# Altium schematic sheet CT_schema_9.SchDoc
size 382 x 278 mm
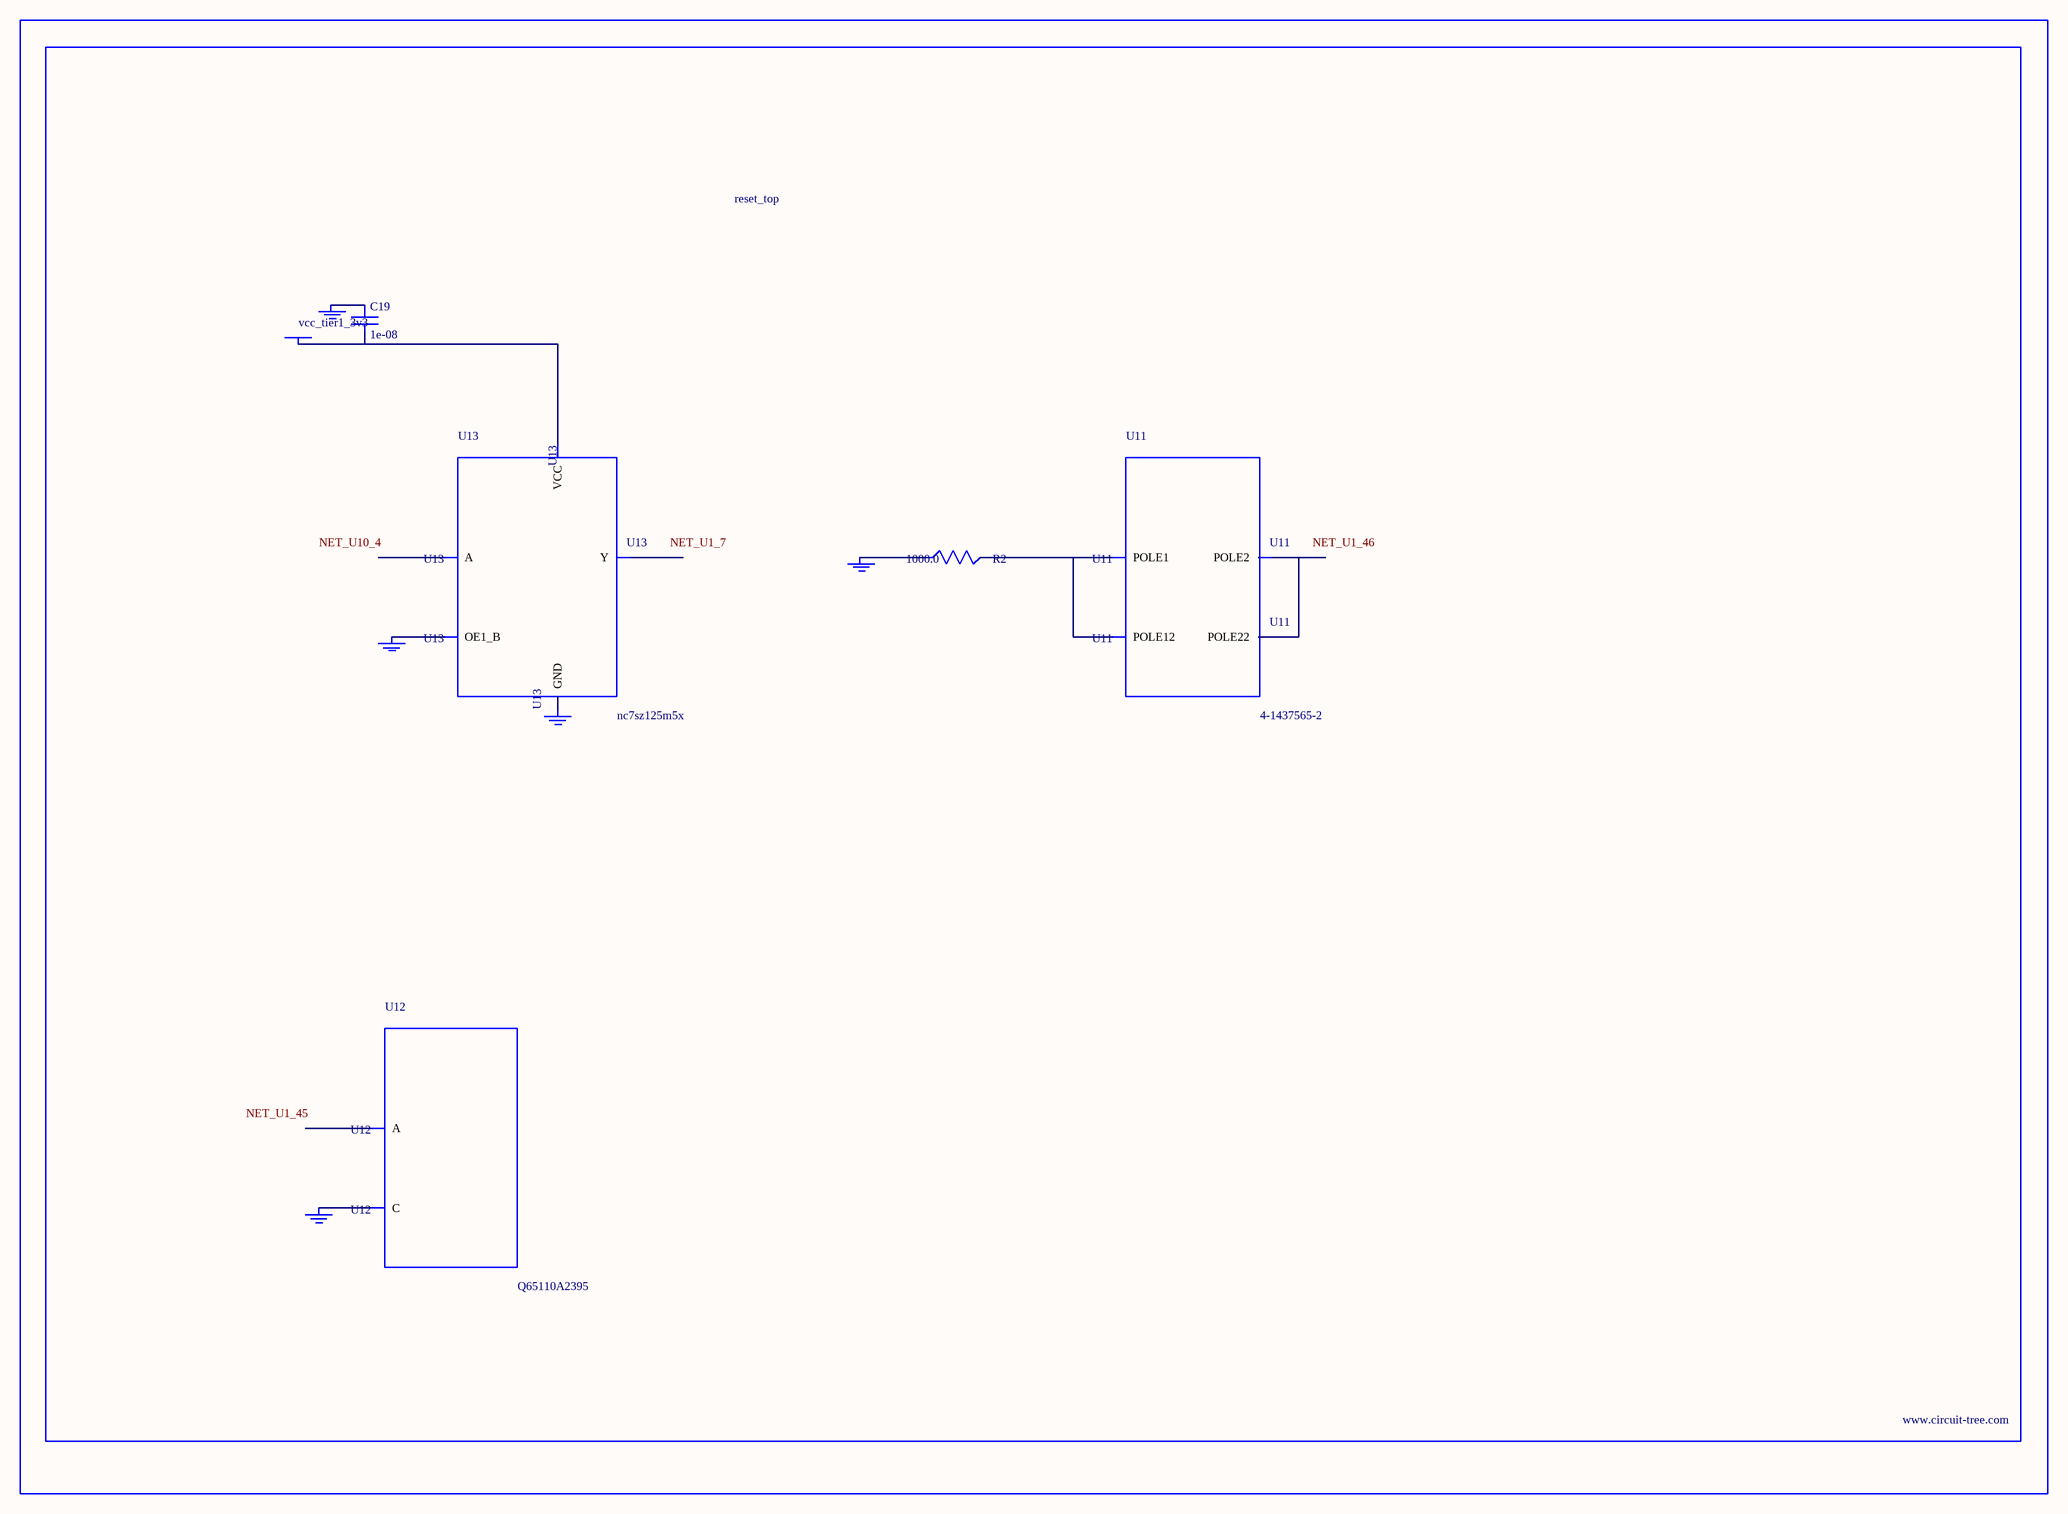
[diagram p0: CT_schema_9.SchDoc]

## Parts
BORDER8  (no value)
C19  1e-08  [C0402]
GND_INSTANCE_8_0  (no value)
GND_INSTANCE_8_1  (no value)
GND_INSTANCE_8_2  (no value)
GND_INSTANCE_8_3  (no value)
GND_INSTANCE_8_4  (no value)
POWER_INSTANCE_8_0  vcc_tier1_3v3
R2  1000.0  [R0603]
U11  4-1437565-2  [SW_4-1437565-2]
U12  Q65110A2395  [LGM67K-G1J2-24-Z]
U13  nc7sz125m5x  [NC7SZ125M5X]

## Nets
NetC19_1: C19.1 GND_INSTANCE_8_2.0(GND)
NetC19_2: C19.2 POWER_INSTANCE_8_0.0(PWR) U13.5(VCC)
NetGND_INSTANCE_8_0_0: GND_INSTANCE_8_0.0(GND) R2.1
NetGND_INSTANCE_8_1_0: GND_INSTANCE_8_1.0(GND) U12.C
NetGND_INSTANCE_8_3_0: GND_INSTANCE_8_3.0(GND) U13.1(OE1_B)
NetGND_INSTANCE_8_4_0: GND_INSTANCE_8_4.0(GND) U13.3(GND)
NetR2_2: R2.2 U11.1(POLE1) U11.2(POLE12)
NetU11_3: U11.3(POLE2) U11.4(POLE22)

Not connected (* = marked no-connect by the designer): U12 A; U13 2(A) 4(Y)

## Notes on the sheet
- Labels drawn without touching a wire or pin: NET_U1_7, NET_U1_45, NET_U1_46, NET_U10_4

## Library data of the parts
BORDER8 = BORDER_PAGE8
C19 = C0402C103K3RAC
GND_INSTANCE_8_0-GND_INSTANCE_8_4 = GND
POWER_INSTANCE_8_0 = PWR
R2 = RC0603JR-071KL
